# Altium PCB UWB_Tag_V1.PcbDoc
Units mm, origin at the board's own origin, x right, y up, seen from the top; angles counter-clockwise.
Board outline 86.23 x 70.61 mm, 2 copper layers (Top Layer, Bottom Layer); 71 components, 55 nets, 304 pads, 29 vias.
Unrouted connection lines stored in the file: 1.
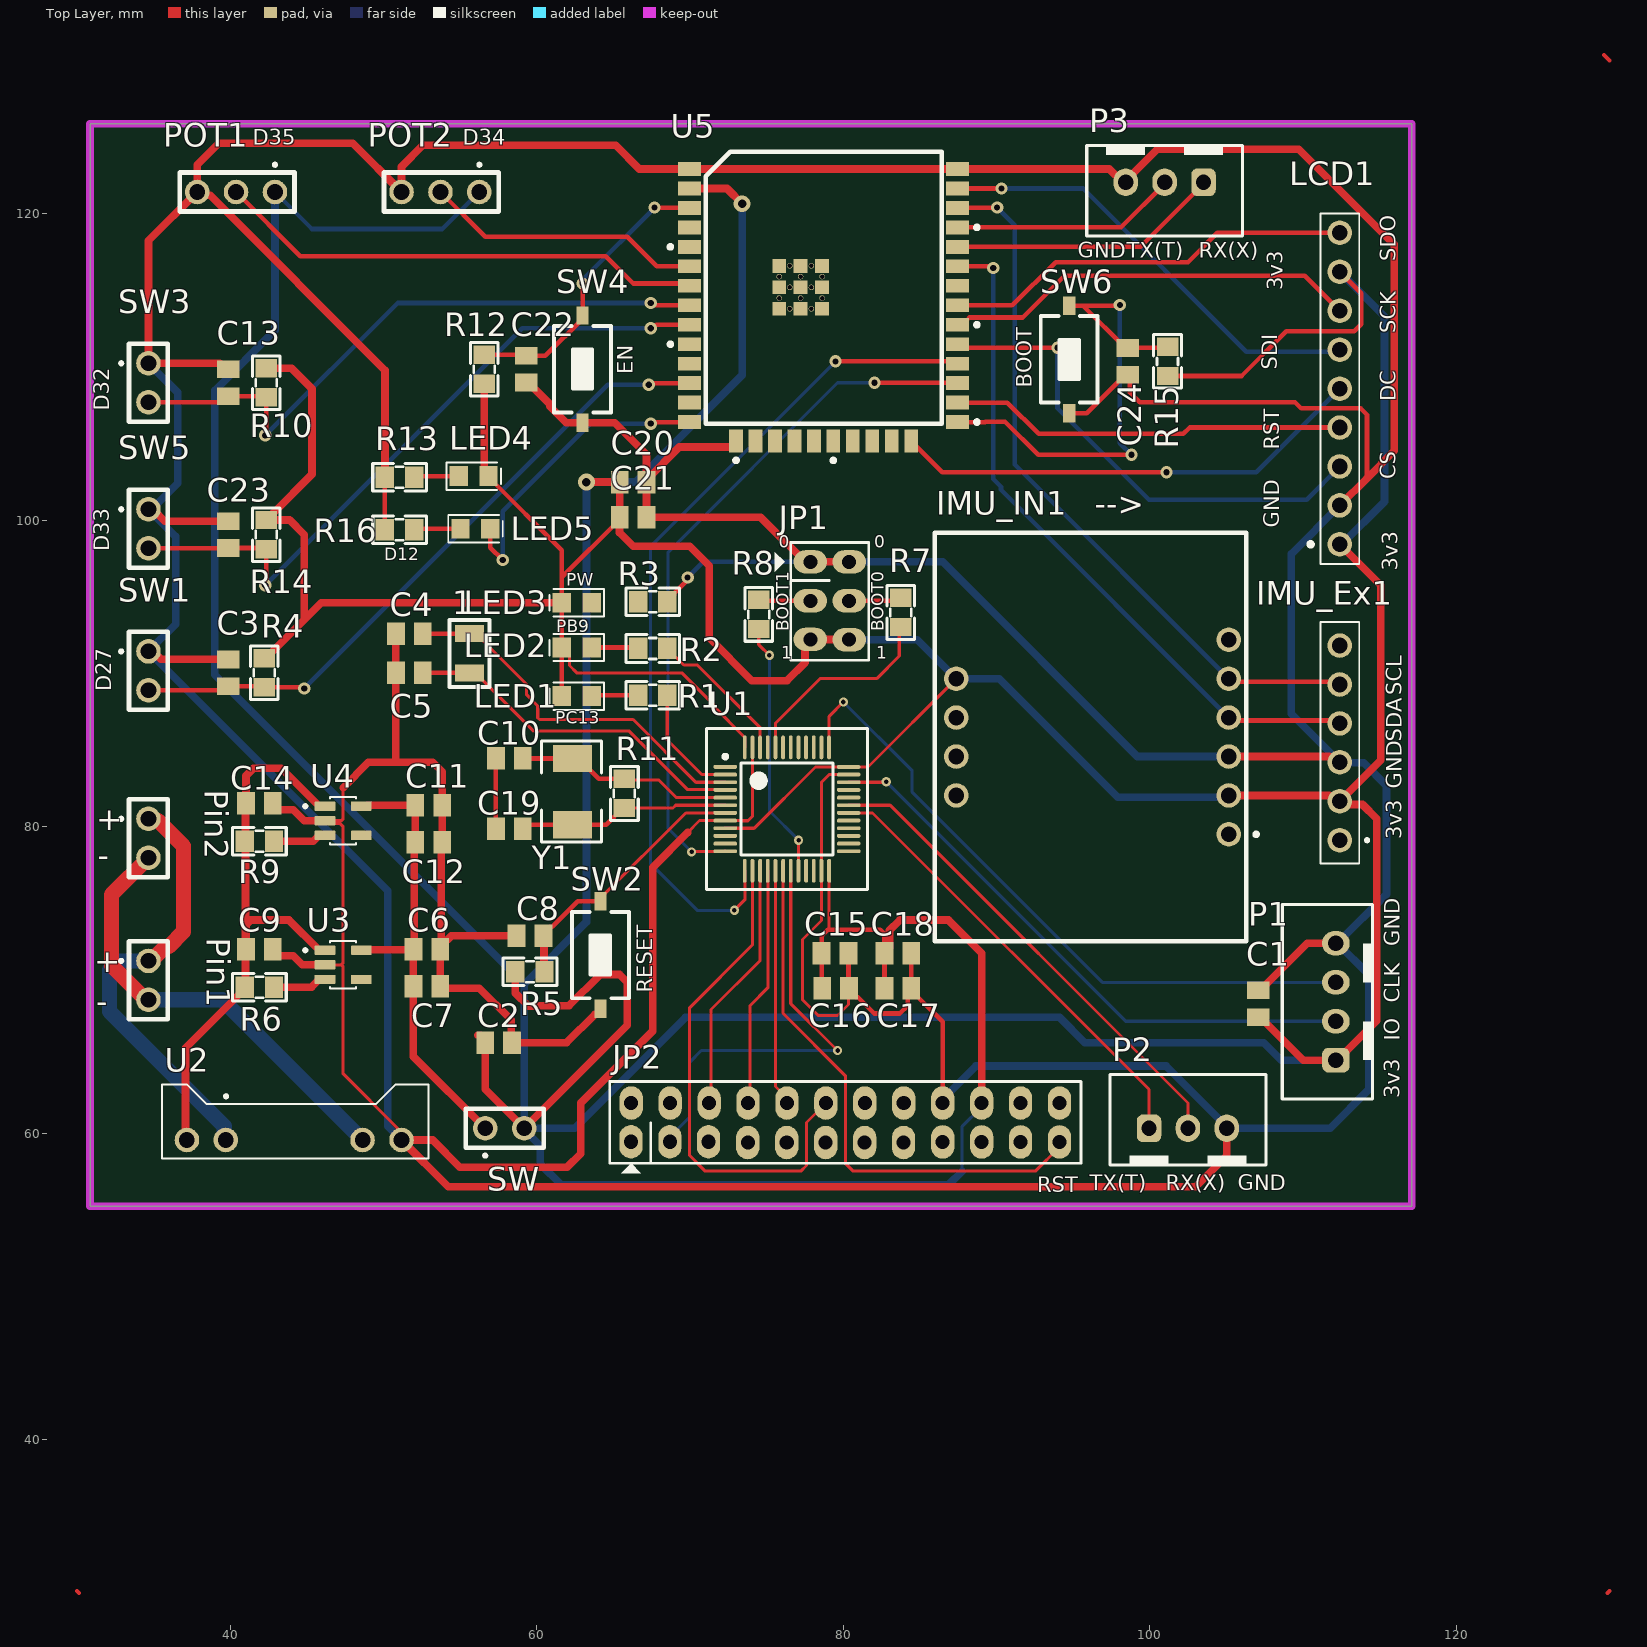
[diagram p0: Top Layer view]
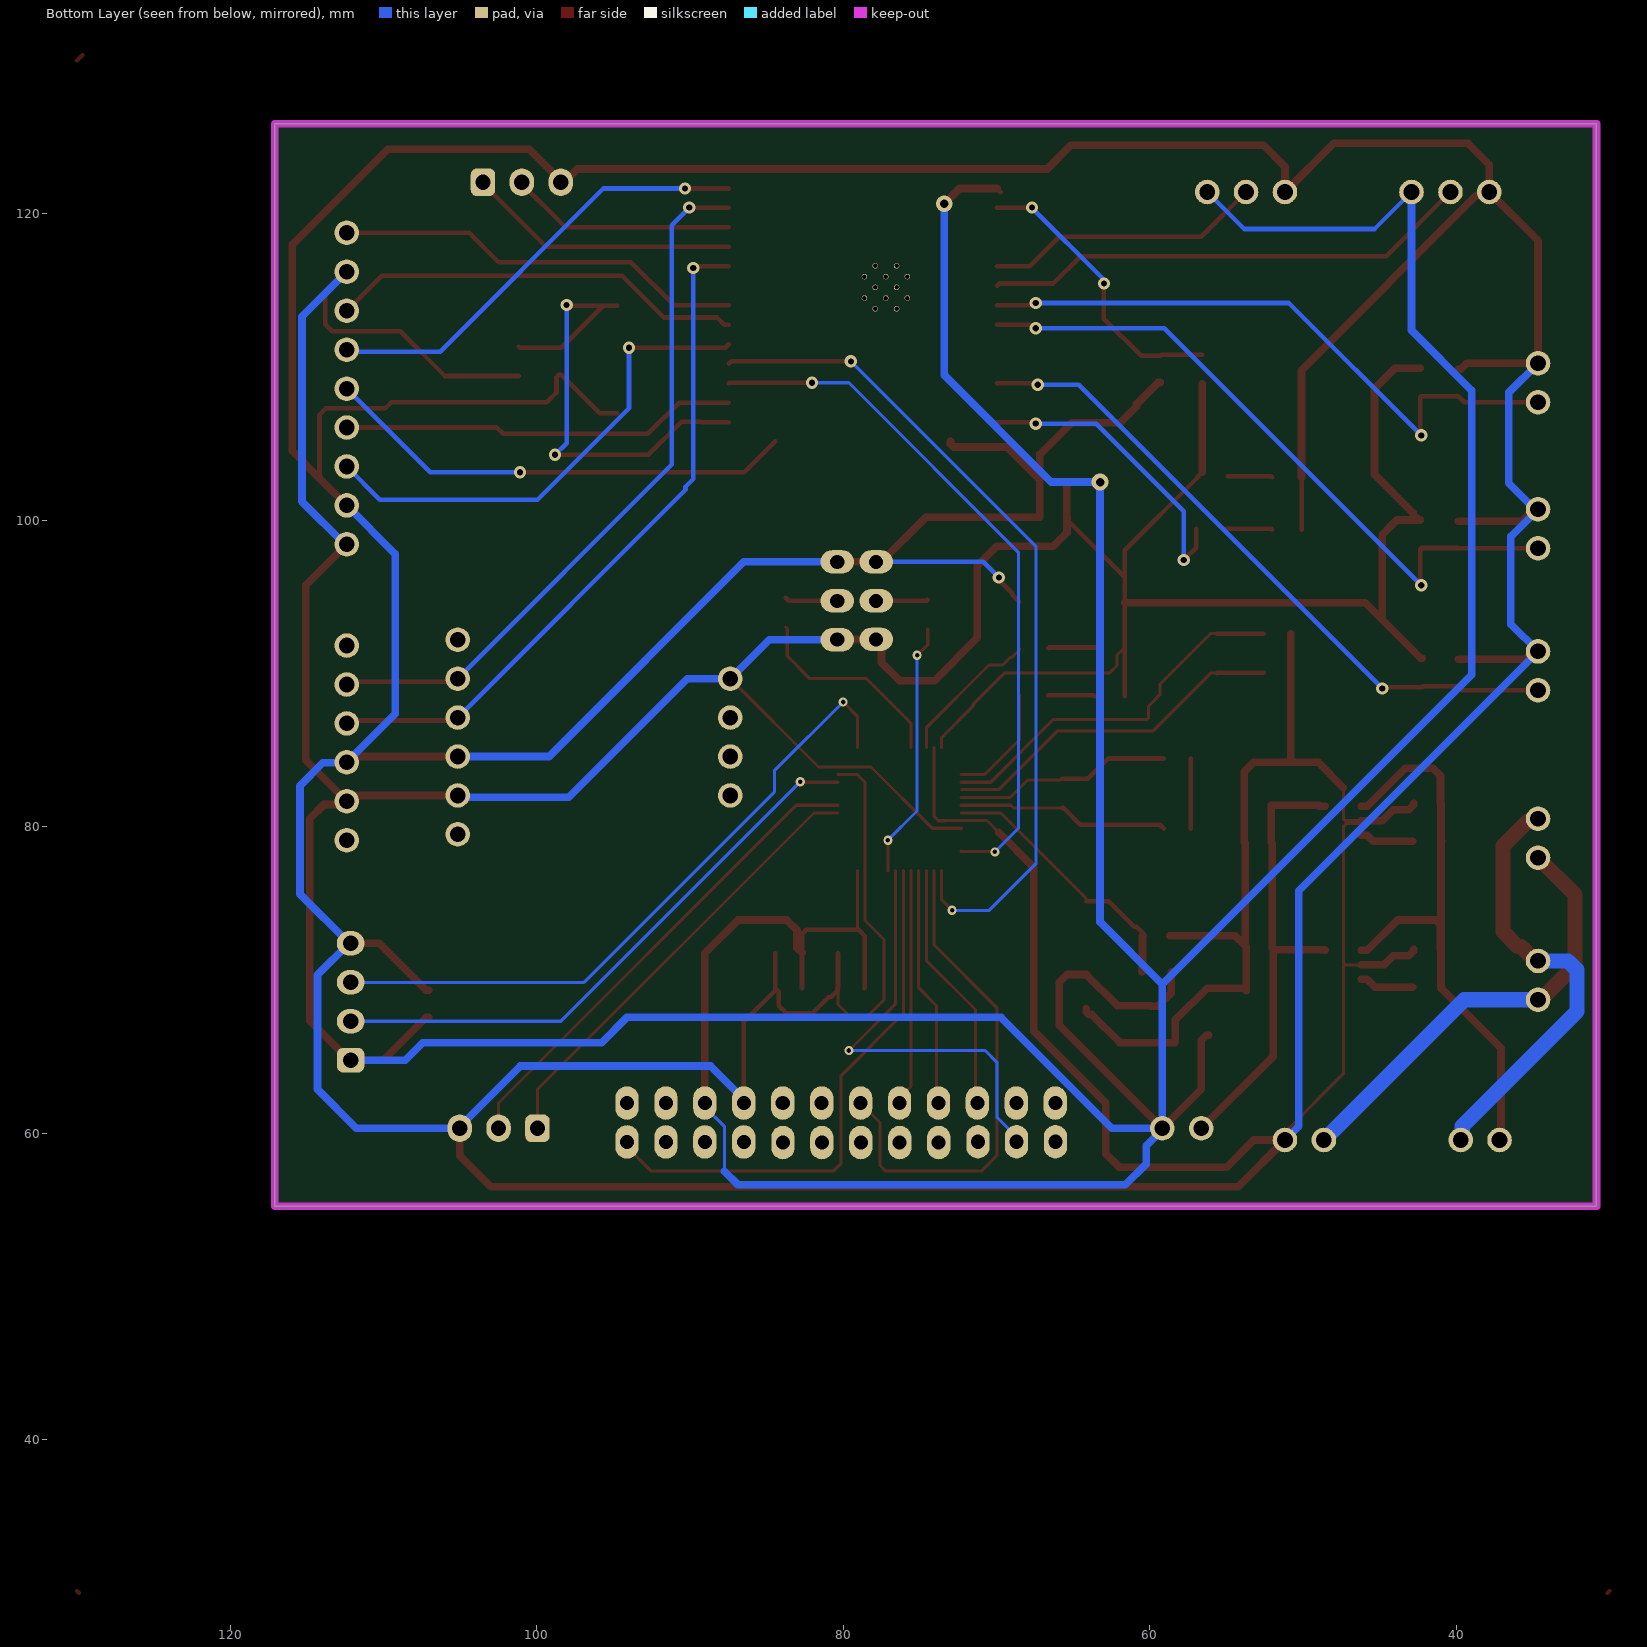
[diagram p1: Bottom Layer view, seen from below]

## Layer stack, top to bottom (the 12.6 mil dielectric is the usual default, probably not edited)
Top Solder: solder mask 0.0102, Solder Resist, Dk 3.5
Top Layer: signal copper 0.0356
Dielectric 1: dielectric 0.32, FR-4, Dk 4.8
Bottom Layer: signal copper 0.0356
Bottom Solder: solder mask 0.0102, Solder Resist, Dk 3.5

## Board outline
30.861,55.245 30.861,125.857 117.094,125.857 117.094,55.245

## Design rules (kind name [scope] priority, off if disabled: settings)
Clearance [All] p1: gap=0.2 ignorepadtopadclearanceinfootprint=FALSE
PolygonConnect [All] p1: connectstyle=Relief reliefconductorwidth=0.254 reliefentries=4 polygonreliefangle="90 Angle" airgapwidth=0.254
RoutingVias [All] p1: holewidth=0.711 width=1.27 viastyle="Through Hole" minholewidth=0.711 minwidth=1.27 maxholewidth=0.711 maxwidth=1.27
SolderMaskExpansion [All] p1: expansion=0.102 istentingtop=FALSE
Width RON [InNetClass('RON')] p1: maxlimit=0.5 minlimit=0.2 preferedwidth=0.3
Width POW [InNetClass('POW')] p2: maxlimit=1 minlimit=0.3 preferedwidth=0.5
30 further rules are at their usual default settings.

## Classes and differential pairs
net class RON: 3V3 BOOT BOOT0 BOOT1 D2/SPI_DC D4/SPI_RST D5/SPI_CS D12/LED1 D18/SPI_SCK D19/SPI_SDO D23/SPI_SDI D27 D32 D33 D34_Pot1 D35_Pot2 DB_RX DB_TX DW_IRQ DW_NSS DW_RESET EN GND MISO MOSI NetC10_1 NetJP1_2 NetJP1_5 NetLED1_2 NetLED2_2 NetLED3_2 NetLED4_2 NetLED5_2 NetR6_2 NetR9_2 O_3V3 OSCIN OSCOUT PB9 PC13 PC14 PC15 RESET RX0 SCK SCL SDA STMRX_ESPTX STMTX-ESPRX SWCLK SWIO TX0 VOUT
net class POW: VBAT+ VBAT-

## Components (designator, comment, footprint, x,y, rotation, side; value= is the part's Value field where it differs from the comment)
1 "ABS07" ABS07 55.626,91.313 r90 top
C1 "10uF" Capacitor_0805 107.061,68.453 r270 top
C2 "0.1uF" Capacitor_0805 57.517,65.913 r0 top
C3 "10uF" Capacitor_0805 39.878,90.043 r90 top
C4 "20pF" Capacitor_0805 51.689,92.583 r0 top
C5 "20pF" Capacitor_0805 51.689,90.043 r0 top
C6 "47uF" Capacitor_0805 52.832,72.009 r0 top
C7 "0.1uF" Capacitor_0805 52.832,69.596 r0 top
C8 "0.1uF" Capacitor_0805 59.563,72.898 r180 top
C9 "0.1uF" Capacitor_0805 41.91,72.009 r0 top
C10 "20pF" Capacitor_0805 58.215,84.455 r0 top
C11 "47uF" Capacitor_0805 52.959,81.407 r0 top
C12 "0.1uF" Capacitor_0805 52.959,78.994 r0 top
C13 "10uF" Capacitor_0805 39.878,108.966 r90 top
C14 "0.1uF" Capacitor_0805 41.91,81.534 r0 top
C15 "0.1uF" Capacitor_0805 79.465,71.755 r0 top
C16 "0.1uF" Capacitor_0805 79.502,69.469 r0 top
C17 "0.1uF" Capacitor_0805 83.566,69.469 r0 top
C18 "0.1uF" Capacitor_0805 83.566,71.755 r0 top
C19 "20pF" Capacitor_0805 58.215,79.883 r0 top
C20 "10uF" Capacitor_0805 66.294,102.489 r0 top
C21 "0.1uF" Capacitor_0805 66.294,100.203 r0 top
C22 "10uF" Capacitor_0805 59.309,109.855 r270 top
C23 "10uF" Capacitor_0805 39.878,99.06 r90 top
C24 "10uF" Capacitor_0805 98.552,110.363 r270 top
IMU_Ex1 "BNO055" BNO055_External 112.395,85.471 r90 top
IMU_IN1 "BNO055" BNO055_Internal 96.266,85.852 r90 top
JP1 "Connector 3x2" JP3x2 79.121,94.742 r270 top
JP2 "Connector 12x2" JP12X2_1 66.167,59.436 r0 top
LCD1 "ILI9341" ILI9341_LCD3.5 112.395,108.585 r0 top
LED1 "Led" "Led 0805 Blue" 62.611,88.519 r0 top
LED2 "Led" "Led 0805 Blue" 62.611,91.694 r0 top
LED3 "Led" "Led 0805 Blue" 62.611,94.615 r0 top
LED4 "Led" "Led 0805 Blue" 55.88,102.87 r180 top
LED5 "Led" "Led 0805 Blue" 56.007,99.441 r180 top
P1 "SWD" HDR/Header/4/BOX 112.141,68.58 r90 top
P2 "UART" HDR/Header/3/BOX 102.489,60.325 r90 top
P3 "UART" HDR/Header/3/BOX 100.965,122.047 r270 top
Pin1 "JP_1x2" JP_1x2 34.671,69.977 r270 top (schematic designator Battery1)
Pin2 "JP_1x2" JP_1x2 34.671,79.248 r270 top (schematic designator Battery2)
POT1 "JP_1x3" JP_1x3 44.323,115.951 r180 top
POT2 "JP_1x3" JP_1x3 57.658,115.951 r180 top
R1 "1k" "tro smd 0805" 67.564,88.646 r0 top
R2 "1k" "tro smd 0805" 67.564,91.694 r0 top
R3 "1k" "tro smd 0805" 67.564,94.742 r0 top
R4 "10k" "tro smd 0805" 42.164,90.043 r90 top
R5 "10k" "tro smd 0805" 59.563,70.485 r180 top
R6 "1k" "tro smd 0805" 41.91,69.596 r0 top
R7 "10k" "tro smd 0805" 83.693,93.98 r90 top
R8 "10k" "tro smd 0805" 74.549,93.853 r270 top
R9 "1k" "tro smd 0805" 41.91,79.121 r0 top
R10 "10k" "tro smd 0805" 42.291,108.966 r90 top
R11 "1M" "tro smd 0805" 65.659,82.169 r90 top
R12 "10k" "tro smd 0805" 56.642,109.855 r270 top
R13 "1k" "tro smd 0805" 51.054,102.743 r180 top
R14 "10k" "tro smd 0805" 42.291,99.06 r90 top
R15 "10k" "tro smd 0805" 101.219,110.363 r270 top
R16 "1k" "tro smd 0805" 51.054,99.314 r180 top
SW "SW_POWER" JP_1x2 57.912,60.325 r0 top (schematic designator jp_1)
SW1 "JP_1x2" JP_1x2 34.671,90.17 r270 top
SW2 "SW" SW1-SMD 64.156,71.628 r90 top value="SW chip 2 pin"
SW3 "JP_1x2" JP_1x2 34.671,108.966 r270 top
SW4 "SW" SW1-SMD 62.992,109.855 r90 top value="SW chip 2 pin"
SW5 "JP_1x2" JP_1x2 34.671,99.441 r270 top
SW6 "SW" SW1-SMD 94.742,110.49 r90 top value="SW chip 2 pin"
U1 "STM32F103C8T6" LQFP48 76.327,81.153 r270 top
U2 "TP4056_charger" TP4056_charger 44.181,48.063 r90 top
U3 "AP2112K-3.3TRG1" SOT95P285X140-5N 47.371,70.993 r0 top
U4 "AP2112K-3.3TRG1" SOT95P285X140-5N 47.371,80.391 r0 top
U5 "ESP32_WROOM_32U" ESP32_WROOM_32U 78.719,114.032 r0 top
Y1 "8Mhz" "Thach Anh 2 chan SMD5032" 62.335,82.296 r90 top value=4Mhz

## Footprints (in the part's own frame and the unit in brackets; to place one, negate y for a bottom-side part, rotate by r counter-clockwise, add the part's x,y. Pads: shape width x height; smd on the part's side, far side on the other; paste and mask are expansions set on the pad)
ABS07 [mm] "HC-49US XTAL"
  rect 1.1x1.9 smd: 1(-1.29,0) 2(1.29,0)
  silkscreen extent -2.19,-1.3 2.18,1.31, body extent -1.6,-0.75 1.6,0.75, height 0.9
BNO055_External [mm]
  round 1.6 hole 1.02 mask+0.1: 1(-6.35,0) 2(-3.81,0) 3(-1.27,0) 4(1.27,0) 5(3.81,0) 6(6.35,0)
  silkscreen extent -7.87,-1.88 7.87,1.27, body extent -8.75,-2.16 8.75,3.59, height 7.1
BNO055_Internal [mm]
  round 1.6 hole 1.02 mask+0.1: 1(-6.35,-8.89) 2(-3.81,-8.89) 3(-1.27,-8.89) 4(1.27,-8.89) 5(3.81,-8.89) 6(6.35,-8.89) 7(3.81,8.89) 8(1.27,8.89) 9(-1.27,8.89) 10(-3.81,8.89)
  silkscreen extent -13.33,-10.77 13.33,10.29, body extent -13.33,-10.12 13.33,10.29, height 9.15
Capacitor_0805 [mm]
  rect 1.16x1.47 smd: 1(-0.875,0) 2(0.875,0)
  body extent -1,-0.6 1,0.6, height 1.2
ESP32_WROOM_32U [mm]
  rect 1.5x0.9 smd: 1(-8.75,8.88) 2(-8.75,7.61) 3(-8.75,6.34) 4(-8.75,5.07) 5(-8.75,3.8) 6(-8.75,2.53) 7(-8.75,1.26) 8(-8.75,-0.01) 9(-8.75,-1.28) 10(-8.75,-2.55) 11(-8.75,-3.82) 12(-8.75,-5.09) 13(-8.75,-6.36) 14(-8.75,-7.63) 25(8.75,-7.63) 26(8.75,-6.36) 27(8.75,-5.09) 28(8.75,-3.82) 29(8.75,-2.55) 30(8.75,-1.28) 31(8.75,-0.01) 32(8.75,1.26) 33(8.75,2.53) 34(8.75,3.8) 35(8.75,5.07) 36(8.75,6.34) 37(8.75,7.61) 38(8.75,8.88)
  rect 0.9x1.5 smd: 15(-5.715,-8.88) 16(-4.445,-8.88) 17(-3.175,-8.88) 18(-1.905,-8.88) 19(-0.635,-8.88) 20(0.635,-8.88) 21(1.905,-8.88) 22(3.175,-8.88) 23(4.445,-8.88) 24(5.715,-8.88)
  rect 0.9x0.9 smd: 39_1(-2.9,2.56) 39_2(-1.5,2.56) 39_3(-0.1,2.56) 39_4(-2.9,1.16) 39_5(-1.5,1.16) 39_6(-0.1,1.16) 39_7(-2.9,-0.24) 39_8(-1.5,-0.24) 39_9(-0.1,-0.24)
  round 0.35 hole 0.3 mask+0: 40_1(-2.2,2.56) 40_2(-0.8,2.56) 40_3(-2.9,1.86) 40_4(-1.5,1.86) 40_5(-0.1,1.86) 40_6(-2.2,1.16) 40_7(-0.8,1.16) 40_8(-2.9,0.46) 40_9(-1.5,0.46) 40_10(-0.1,0.46) 40_11(-2.2,-0.24) 40_12(-0.8,-0.24)
  silkscreen extent -10.1,-10.23 10.1,10, body extent -9,-9.13 9,10.07, height 3.35
HDR/Header/3/BOX [mm]
  rrect50% 1.8x1.6 hole 1: 1(0,2.54)
  oval 1.8x1.6 hole 1: 2(0,0) 3(0,-2.54)
  silkscreen extent -2.41,-5.08 3.5,5.08, body extent -2.29,-5 3.41,5, height 7
HDR/Header/4/BOX [mm]
  rrect50% 1.6x1.8 hole 1: 1(-3.81,0)
  oval 1.6x1.8 hole 1: 2(-1.27,0) 3(1.27,0) 4(3.81,0)
  silkscreen extent -6.35,-2.41 6.35,3.5, body extent -6.25,-2.3 6.25,3.4, height 7
ILI9341_LCD3.5 [mm]
  round 1.6 hole 1.02 mask+0.1: 1(0,-10.16) 2(0,-7.62) 3(0,-5.08) 4(0,-2.54) 5(0,0) 6(0,2.54) 7(0,5.08) 8(0,7.62) 9(0,10.16)
  silkscreen extent -2.03,-11.43 1.27,11.43, body extent -3.56,-12.5 2.19,12.5, height 7.1
JP3x2 [mil] "Connector 3x2"
  oval 60x86 hole 36: 1(-100,-50) 2(0,-50) 3(99,-50) 4(-100,50) 5(0,50) 6(100,50)
  silkscreen extent -150,-141 153,100, body extent -150,-100 150,100, height 335
JP12X2_1 [mil]
  oval 60x86 hole 36: 1(-0.5,0.5) 2(99.5,0.5) 3(198.5,0.5) 4(299.5,-1.5) 5(399.5,-1.5) 6(499.5,-1.5) 7(599.5,-1.5) 8(699.5,-1.5) 9(800,0) 10(900,0) 11(1000,0) 12(1100,0) 13(0,100) 14(100,100) 15(200,100) 16(300,100) 17(400,100) 18(500,100) 19(600,100) 20(700,100) 21(800,100) 22(900,100) 23(1000,100) 24(1100,100)
  silkscreen extent -55,-80 1155,155, body extent -55,-47 1155,150, height 366
JP_1x2 [mm] "CWF2 (DS1069-1x2)"
  round 1.6 hole 1.02 mask+0.1: 1(-1.27,0) 2(1.27,0)
  silkscreen extent -2.54,-1.88 2.54,1.27, body extent -3.77,-2.2 3.73,3.55, height 7
JP_1x3 [mm] "CWF3 (DS1069-1x3)"
  round 1.6 hole 1.02 mask+0.1: 1(1.397,-5.461) 2(3.937,-5.461) 3(6.477,-5.461)
  silkscreen extent 0.13,-7.34 7.62,-4.19, body extent -1.06,-7.66 8.94,-1.9, height 7.1
"Led 0805 Blue" [mm]
  rect 1.2x1.3 smd: 1(-0.975,0) 2(0.975,0)
  silkscreen extent -1.78,-0.89 1.78,0.89, body extent -1.01,-0.62 1.01,0.63, height 1.1
LQFP48 [mm]
  oval 0.25x1.55 smd: 1(-2.75,-4.025) 2(-2.25,-4.025) 3(-1.75,-4.025) 4(-1.25,-4.025) 5(-0.75,-4.025) 6(-0.25,-4.025) 7(0.25,-4.025) 8(0.75,-4.025) 9(1.25,-4.025) 10(1.75,-4.025) 11(2.25,-4.025) 12(2.75,-4.025) 25(2.75,4.025) 26(2.25,4.025) 27(1.75,4.025) 28(1.25,4.025) 29(0.75,4.025) 30(0.25,4.025) 31(-0.25,4.025) 32(-0.75,4.025) 33(-1.25,4.025) 34(-1.75,4.025) 35(-2.25,4.025) 36(-2.75,4.025)
  oval 1.55x0.25 smd: 13(4.025,-2.75) 14(4.025,-2.25) 15(4.025,-1.75) 16(4.025,-1.25) 17(4.025,-0.75) 18(4.025,-0.25) 19(4.025,0.25) 20(4.025,0.75) 21(4.025,1.25) 22(4.025,1.75) 23(4.025,2.25) 24(4.025,2.75) 37(-4.025,2.75) 38(-4.025,2.25) 39(-4.025,1.75) 40(-4.025,1.25) 41(-4.025,0.75) 42(-4.025,0.25) 43(-4.025,-0.25) 44(-4.025,-0.75) 45(-4.025,-1.25) 46(-4.025,-1.75) 47(-4.025,-2.25) 48(-4.025,-2.75)
  silkscreen extent -5.25,-5.25 5.25,5.25, body extent -4.5,-4.5 4.5,4.5, height 1.5
SOT95P285X140-5N [mm]
  rrect15% 1.35x0.6 smd: 1(-1.185,0.95) 2(-1.185,0) 3(-1.185,-0.95) 4(1.185,-0.95) 5(1.185,0.95)
  silkscreen extent -2.57,-1.55 0.85,1.55, body extent -1.5,-1.4 1.5,1.4, height 1.4
SW1-SMD [mm]
  rect 1.2x0.8 smd: 1(-3.5,0) 2(3.5,0)
  silkscreen extent -2.82,-1.85 2.82,1.85, body extent -3.05,-1.85 3.05,1.85, height 2.5
"Thach Anh 2 chan SMD5032" [mil]
  rect 70x100 smd: 1(-85,0) 2(85,0)
  silkscreen extent -130,-75 130,80, body extent -98,-63 98,63, height 51
TP4056_charger [mm]
  round 1.6 hole 1.02 mask+0.1: 1(11.5,4.46) 2(11.5,-4.46) 3(11.5,7) 4(11.5,-7)
  silkscreen extent 10.29,-8.76 15.11,8.64, body extent -14.19,-8.76 15.11,8.64, height 9.34
"tro smd 0805" [mm]
  rect 1.2x1.4 smd: 1(-0.946,-0.061) 2(0.954,-0.061)
  silkscreen extent -1.75,-0.97 1.75,0.84, body extent -1.56,-0.76 1.44,0.64, height 0.53

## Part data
1: "SMD Quartz Crystal"
C1 C2 C3 C4 C5 C6 C7 C8 C9 C10 C11 C12 C13 C14 C15 C16 C17 C18 C19 C20 C21 C22 C23 C24: library part Capacitor_0805, "Capacitor; Ceramic; Cap; .220uF; Tol 10%; SMT; Vol-Rtg 50V; X7R; Tape And Reel"
IMU_Ex1: library part BNO055_External
JP1: library part JP3x2
JP2: library part JP12x2
LCD1: library part ILI9341_LCD3.5
LED1 LED2 LED3 LED4 LED5: "Typical LED"
P1: library part "Header 4_1", "Header, 4-Pin"
P2 P3: library part "Header 3", "Header, 3-Pin"
R1 R2 R3 R6 R9 R13 R16: library part "Tro 0805 1% 1k", "Dán"
R4 R5 R7 R8 R10 R12 R14 R15: library part "Tro 0805 1% 10k", "Dán"
R11: library part "Tro 0805 1% 1M", "Dán"
SW: library part JP_1x2
SW2 SW4 SW6: library part SW2, "Switch button 2 pin"
U1: "STM32 ARM-based 32-bit MCU with ARM 32-bit Cortex-M3 Microcontroller, 128 Kbytes Flash, 48-pin LQFP, Industrial Temperature"
U3 U4: "Linear Voltage Regulator IC Positive Fixed 1 Output 600mA SOT-25", Package="SOT-753 Diodes Inc."
U5: "Bluetooth, WiFi 802.11b/g/n, Bluetooth v4.2 +EDR, Class 1, 2 and 3 Transceiver Module 2.4GHz ~ 2.5GHz Antenna Not Included, U.FL Surface Mount"
Y1: library part "Thach Anh 2 chan SMD 5032", "Crystal For all Crystal 2pin."

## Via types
v1: diameter 0.8, hole 0.4, Top Layer to Bottom Layer, 20 vias
v2: diameter 0.6, hole 0.3, Top Layer to Bottom Layer, 7 vias
v3: diameter 1.1, hole 0.55, Top Layer to Bottom Layer, 2 vias

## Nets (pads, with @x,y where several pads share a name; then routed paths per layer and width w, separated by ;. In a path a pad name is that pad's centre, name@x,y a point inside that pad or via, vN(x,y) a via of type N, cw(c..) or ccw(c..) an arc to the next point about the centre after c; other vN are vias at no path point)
3V3: C1.2 C2.1 C15.1 C16.1 C17.1 C18.1 C20.1 C21.1 IMU_Ex1.2 IMU_IN1.2 IMU_IN1.7 JP1.3 JP1.6 JP2.22 LCD1.1 LCD1.8 LED1.1 LED2.1 LED3.1 LED4.1 P1.1 POT1.1 POT2.1 R4.2 R5.2 R10.2 R12.2 R14.2 R15.2 SW.2 U1.9 U1.24 U1.36 U1.48 U5.2 | length 559.8
  Top Layer w0.2: LED2.1 62.136,91.194 62.136,90.518 62.611,90.043 69.469,90.043 71.518,87.994 71.518,87.887 73.577,85.828 U1.48 ; U1.9 74.188,79.903 78.188,83.903 U1.36 81.617,83.903 IMU_IN1.7 ; 78.994,73.279 79.077,73.362 U1.24 ; JP2.22@89.027,61.722 JP2.22
  Top Layer w0.3: LED4.1@56.581,103.144 LED4.1 56.855,102.82 61.636,98.039 61.636,96.265 ; LED1.1 LED2.1 LED3.1 61.636,96.265 ; C21.1@65.405,100.189 65.405,100.034 61.636,96.265 ; U5.2@69.739,121.412 U5.2 ; C16.1 78.59,69.506 C15.1 78.59,72.875 78.994,73.279 82.423,73.279 82.677,73.025 82.677,71.769 C18.1 C17.1 ; R15.2 105.98,109.409 108.902,112.331 113.347,112.331 113.792,112.776 113.792,114.808 LCD1.8
  Top Layer w0.5: R4.2 42.325,90.997 45.942,94.615 LED3.1 ; R14.2 R14.2@42.452,100.014 ; R10.2 44.004,109.92 45.339,108.585 45.339,103.002 42.802,100.464 42.802,100.364 R14.2@42.452,100.014 ; 44.831,93.604 44.831,99.06 43.877,100.014 R14.2@42.452,100.014 ; C2.1@56.157,66.398 56.312,66.398 56.642,66.068 C2.1 56.642,62.865 SW.2 ; LED4.1@56.581,103.144 R12.2 ; R5.2@58.5,70.438 R5.2 58.609,69.153 59.483,68.279 59.897,68.279 59.944,68.326 62.103,68.326 64.135,70.358 65.405,70.358 65.913,69.85 65.913,67.056 SW.2 ; SW.2@59.182,60.248 SW.2 ; v3@63.627,102.489 C20.1 C21.1 C21.1@65.405,100.189 ; C21.1@65.405,100.034 65.405,99.187 66.294,98.298 69.977,98.298 71.247,97.028 71.247,92.329 74.041,89.535 76.327,89.535 77.507,90.715 77.507,91.884 JP1.3 77.864,92.215 80.378,92.215 JP1.6 ; U5.2 72.414,121.642 v3(73.406,120.65) ; C18.1@82.677,71.769 83.019,72.111 83.019,73.24 83.693,73.914 86.868,73.914 89.027,71.755 JP2.22 ; IMU_IN1.2 111.716,82.042 112.097,81.661 IMU_Ex1.2 ; C1.2 107.216,67.578 110.024,64.77 P1.1 112.241,64.77 114.808,67.337 114.808,80.518 113.875,81.451 112.605,81.451 IMU_Ex1.2 ; LCD1.1 115.062,95.758 115.062,84.328 IMU_Ex1.2
  Bottom Layer w0.2: 87.757,57.531 87.757,60.452 JP2.22@89.027,61.722
  Bottom Layer w0.3: POT1.1 45.339,118.999 53.848,118.999 POT2.1
  Bottom Layer w0.5: POT1.1 42.926,112.395 38.989,108.458 38.989,89.916 59.182,69.723 ; SW.2@59.182,60.248 60.24,59.191 60.24,57.997 61.595,56.642 86.868,56.642 87.757,57.531 ; v3(73.406,120.65) 73.406,109.474 66.421,102.489 v3(63.246,102.489) 63.246,73.787 59.182,69.723 ; JP1.6 84.836,92.202 IMU_IN1.7 90.17,89.662 97.917,81.915 105.029,81.915 IMU_IN1.2 ; P1.1 108.585,64.77 107.442,65.913 95.758,65.913 94.107,67.564 69.711,67.564 62.472,60.325 SW.2 59.182,69.723 ; LCD1.1 112.522,98.425 115.316,101.219 115.316,113.284 LCD1.8
BOOT: C24.1 R15.1 SW6.2 U5.25 | length 32.3
  Top Layer w0.3: U5.25 89.257,106.402 89.281,106.426 90.551,106.426 92.71,104.267 v1(98.806,104.267) ; SW6.2 95.645,113.99 ; v1(98.044,114.046) 97.988,113.99 95.645,113.99 ; R15.1 101.088,111.238 C24.1 98.397,111.238 95.645,113.99
  Bottom Layer w0.3: v1(98.044,114.046) 98.044,105.029 v1(98.806,104.267)
BOOT0: R7.1 U1.44 | length 13.4
  Top Layer w0.2: U1.44 75.577,86.753 78.486,89.662 82.179,89.662 83.654,91.137 83.654,92.934 R7.1
BOOT1: R8.2 U1.20 | length 16.9
  Top Layer w0.2: R8.2 74.488,91.882 v2(75.184,91.186) ; U1.20 77.077,79.109 v2(77.089,79.121)
  Bottom Layer w0.2: v2(75.184,91.186) 75.184,81.026 v2(77.089,79.121)
D2/SPI_DC: LCD1.5 U5.24 | length 31.1
  Top Layer w0.3: U5.24 86.462,103.124 v1(101.092,103.124)
  Bottom Layer w0.3: v1(101.092,103.124) 106.934,103.124 LCD1.5
D4/SPI_RST: LCD1.4 U5.26 | length 25.9
  Top Layer w0.3: U5.26 90.702,107.672 92.743,105.631 102.186,105.631 102.6,106.045 LCD1.4
D5/SPI_CS: LCD1.3 U5.29 | length 32.3
  Top Layer w0.3: U5.29 87.699,111.252 v1(93.98,111.252)
  Bottom Layer w0.3: v1(93.98,111.252) 93.98,107.315 99.949,101.346 110.236,101.346 LCD1.3
D12/LED1: LED5.1 U5.14 | length 20.1
  Top Layer w0.3: LED5.1 56.982,98.212 v1(57.785,97.409) ; v1(67.437,106.299) 67.54,106.402 U5.14
  Bottom Layer w0.3: v1(57.785,97.409) 57.785,100.584 63.5,106.299 v1(67.437,106.299)
D18/SPI_SCK: LCD1.7 U5.30 | length 27.2
  Top Layer w0.3: U5.30 87.769,112.752 88.239,113.222 91.704,113.222 94.433,115.951 110.109,115.951 LCD1.7
D19/SPI_SDO: LCD1.9 U5.31 | length 26.9
  Top Layer w0.3: U5.31 91.035,114.022 93.853,116.84 102.489,116.84 104.394,118.745 LCD1.9
D23/SPI_SDI: LCD1.6 U5.37 | length 29.5
  Top Layer w0.3: U5.37 v1(90.321,121.642) v1@90.424,121.539
  Bottom Layer w0.3: v1(90.321,121.642) 95.655,121.642 106.299,110.998 112.268,110.998 LCD1.6
D27: C3.1 R4.1 SW1.2 U5.12 | length 43.7
  Top Layer w0.2: R4.1@42.154,89.168 R4.1
  Top Layer w0.3: SW1.2 39.61,88.9 C3.1 R4.1@42.154,89.168 ; R4.1 44.761,89.097 v1(44.831,89.027) ; v1(67.31,108.839) 67.413,108.942 U5.12
  Bottom Layer w0.3: v1(44.831,89.027) 64.643,108.839 v1(67.31,108.839)
D32: C13.1 R10.1 SW3.2 U5.8 | length 41.7
  Top Layer w0.3: SW3.2 39.483,107.696 C13.1 42.281,108.091 R10.1 42.352,105.598 v1(42.291,105.537) ; v1(67.437,114.173) 67.588,114.022 U5.8
  Bottom Layer w0.3: v1(42.291,105.537) 50.927,114.173 v1(67.437,114.173)
D33: C23.1 R14.1 SW5.2 U5.9 | length 44.5
  Top Layer w0.3: SW5.2 39.864,98.171 C23.1 42.281,98.185 R14.1 42.352,95.819 v1(42.291,95.758) ; v1@67.691,112.649 67.794,112.752 U5.9
  Bottom Layer w0.3: v1(42.291,95.758) 59.055,112.522 v1(67.437,112.522)
D34_Pot1: POT2.2 U5.6 | length 18.3
  Top Layer w0.3: POT2.2 56.642,118.491 65.913,118.491 67.842,116.562 U5.6
D35_Pot2: POT1.2 U5.7 | length 32.1
  Top Layer w0.3: POT1.2 44.577,117.221 64.516,117.221 66.294,115.443 69.818,115.443 U5.7
DB_RX: P2.2 U1.31 | length 31.8
  Top Layer w0.2: U1.31 83.062,81.403 102.489,61.976 P2.2
DB_TX: P2.1 U1.30 | length 29.6
  Top Layer w0.2: U1.30 81.911,80.903 99.949,62.865 P2.1
DW_IRQ: JP2.2 U1.19 | length 28.7
  Top Layer w0.2: U1.19 76.577,68.457 v2(79.629,65.405)
  Bottom Layer w0.2: JP2.2 68.694,59.779 69.977,61.062 69.977,64.643 70.739,65.405 v2(79.629,65.405)
DW_NSS: JP2.18 U1.14 | length 33.1
  Top Layer w0.2: U1.14 74.077,72.299 69.977,68.199 69.977,58.547 70.993,57.531 77.226,57.531 77.597,57.902 77.597,60.706 JP2.18
DW_RESET: JP2.12 U1.18 | length 35.9
  Top Layer w0.2: U1.18 76.077,67.814 80.137,63.754 80.137,58.029 80.254,57.912 80.264,57.912 80.645,57.531 92.532,57.531 94.107,59.106 JP2.12
EN: C22.1 R12.1 SW4.2 U5.3 | length 18.9
  Top Layer w0.3: R12.1 59.238,110.801 C22.1 60.567,110.73 62.992,113.155 SW4.2 v1(62.992,115.443) ; v1(67.691,120.396) 69.945,120.396 U5.3
  Bottom Layer w0.3: v1(62.992,115.443) 63.088,115.539 63.088,115.793 v1(67.691,120.396)
GND: C1.1 C2.2 C3.2 C4.1 C5.1 C6.2 C7.2 C8.2 C9.2 C11.2 C12.2 C13.2 C14.2 C15.2 C16.2 C17.2 C18.2 C20.2 C21.2 C22.2 C23.2 C24.2 IMU_Ex1.3 IMU_IN1.3 JP1.1 JP1.4 JP2.21 LCD1.2 P1.4 P2.3 P3.3 POT1.3 POT2.3 R3.2 R13.2 R16.2 SW1.1 SW2.1 SW3.1 SW4.1 SW5.1 SW6.1 U1.8 U1.23 U1.35 U1.47 U2.4 U3.2 U4.2 U5.1 U5.15 U5.38 | length 645.6
  Top Layer w0.2: U3.2 47.244,70.993 ; 47.371,82.55 47.371,80.518 47.244,80.391 U4.2 46.357,80.22 47.161,80.22 47.371,80.01 47.371,71.12 47.244,70.993 ; U2.4 50.913,59.831 50.913,60.339 47.371,63.881 47.371,70.876 47.254,70.993 47.244,70.993 ; 69.85,79.629 70.624,80.403 U1.8 72.309,80.396 73.377,80.396 73.382,80.391 73.787,80.391 74.077,80.681 U1.47 ; C16.2@80.34,69.506 80.34,68.402 79.629,67.691 78.359,67.691 77.343,68.707 77.343,72.644 78.577,73.878 U1.23 78.577,80.34 78.569,80.348 78.569,82.887 79.085,83.403 U1.35
  Top Layer w0.3: R16.2 R13.2 ; R3.2 68.968,95.131 68.968,95.231 69.754,96.017 69.754,96.17 v1(69.85,96.266) ; C15.2 80.34,69.506 C16.2 80.377,69.314 80.807,68.884 80.962,68.884 82.028,67.818 83.693,67.818 84.201,68.326 84.201,69.229 C17.2 ; C18.2 C17.2 ; JP2.21 86.487,67.268 84.441,69.314 C17.2 ; SW6.1 95.899,106.99 98.397,109.488 C24.2 98.707,109.333 98.707,108.331 99.342,107.696 109.474,107.696 109.879,107.291 113.768,107.291 114.173,106.885 114.173,102.743
  Top Layer w0.5: SW1.1 34.969,91.44 35.491,90.918 C3.2 ; SW5.1 34.969,100.711 35.745,99.935 C23.2 ; C13.2 39.723,109.841 39.328,110.236 SW3.1 34.671,118.237 POT1.3 ; C9.2 42.785,71.912 43.115,71.582 44.115,71.582 44.704,70.993 U3.2 ; C14.2 42.785,81.437 43.115,81.107 44.115,81.107 44.831,80.391 U4.2 ; 47.371,82.55 49.022,84.201 50.8,84.201 ; R13.2 50.1,109.793 38.691,121.202 38.056,121.202 POT1.3 ; C4.1 C5.1 50.814,84.215 50.8,84.201 ; C7.2@53.707,69.314 53.862,69.469 56.261,69.469 58.332,67.398 58.332,65.973 C2.2 61.941,65.913 63.806,67.778 64.006,67.778 64.156,67.928 SW2.1 ; C7.2@53.707,69.469 C7.2 C6.2 53.707,72.164 C6.2@53.77,72.227 ; C8.2 54.441,72.898 C6.2@53.77,72.227 ; C22.2 59.464,108.98 60.864,107.58 60.864,107.425 61.934,106.355 SW4.1 65.095,106.355 67.169,104.281 C20.2@67.169,102.644 ; 69.85,79.629 67.564,77.343 67.564,66.675 62.865,61.976 62.865,58.674 61.976,57.785 54.991,57.785 53.213,59.563 U2.4 54.229,56.515 102.997,56.515 105.029,58.547 P2.3 ; U5.15 73.004,104.975 72.804,104.775 69.3,104.775 C20.2@67.169,102.644 ; JP1.4 JP1.1 77.521,97.282 74.6,100.203 C21.2 C20.2 C20.2@67.169,102.644 ; IMU_IN1.3 111.716,84.582 112.097,84.201 IMU_Ex1.3 ; C1.1 107.216,69.328 110.278,72.39 P1.4 ; LCD1.2 114.173,102.743 115.951,104.521 115.951,117.983 109.728,124.206 100.484,124.206 98.425,122.147 P3.3 98.227,122.047 97.362,122.912 U5.38 U5.1 66.699,122.912 65.151,124.46 52.578,124.46 51.181,123.063 POT2.3 48.006,124.587 39.243,124.587 37.846,123.19 POT1.3 ; 50.8,84.201 53.213,84.201 53.834,83.58 C11.2 C12.2 53.77,78.93 C6.2@53.77,72.227
  Bottom Layer w0.3: v1(69.85,96.266) 70.866,97.282 JP1.1
  Bottom Layer w0.5: SW3.1 36.576,108.331 36.576,102.401 34.886,100.711 SW5.1 36.449,98.933 36.449,93.218 SW1.1 50.292,75.819 50.292,60.452 U2.4 ; JP1.4 86.487,97.282 99.187,84.582 IMU_IN1.3 ; JP2.21 86.487,62.23 88.646,64.389 101.065,64.389 105.029,60.425 P2.3 111.76,60.325 114.3,62.865 114.3,70.331 P1.4@112.241,72.39 ; P1.4 P1.4@112.241,72.39 ; LCD1.2 109.22,97.79 109.22,87.376 IMU_Ex1.3 112.421,84.175 113.945,84.175 115.443,82.677 115.443,75.592 P1.4@112.241,72.39
MISO: JP2.16 U1.16 | length 16
  Top Layer w0.2: JP2.16@73.787,62.306 JP2.16 73.914,62.103 73.914,68.326 75.077,69.489 U1.16
MOSI: JP2.17 U1.17 | length 15.5
  Top Layer w0.2: U1.17 75.577,63.058 76.327,62.308 JP2.17
NetC10_1: C10.1 C19.1 | length 4.6
  Top Layer w0.3: C19.1 C10.1
NetJP1_2: JP1.2 R8.1 | length 3.4
  Top Layer w0.3: R8.1 74.545,94.742 JP1.2
NetJP1_5: JP1.5 R7.2 | length 3.4
  Top Layer w0.3: JP1.5 83.561,94.742 R7.2
NetLED1_2: LED1.2 R1.1 | length 3.1
  Top Layer w0.3: LED1.2 63.652,88.585 R1.1
NetLED2_2: LED2.2 R2.1 | length 3.1
  Top Layer w0.3: LED2.2 66.558,91.694 R2.1
NetLED3_2: LED3.2 R3.1
NetLED4_2: LED4.2 R13.1 | length 2.9
  Top Layer w0.3: R13.1 52.066,102.87 LED4.2
NetLED5_2: LED5.2 R16.1 | length 3.1
  Top Layer w0.3: R16.1 52.066,99.441 LED5.2
NetR6_2: R6.2 U3.3 | length 3.5
  Top Layer w0.5: R6.2 45.303,69.535 45.811,70.043 U3.3
NetR9_2: R9.2 U4.3 | length 3.5
  Top Layer w0.5: R9.2 45.43,79.06 45.811,79.441 U4.3
O_3V3: C6.1 C7.1 C11.1 C12.1 SW.1 U3.5 U4.5 | length 30
  Top Layer w0.5: U3.5 48.589,71.976 51.924,71.976 C6.1 52.021,72.072 52.021,78.93 C12.1 C11.1 48.997,81.407 48.931,81.341 U4.5 ; C6.1@51.957,71.976 51.957,69.469 51.957,66.802 51.957,65.01 SW.1
OSCIN: C10.2 R11.2 U1.5 Y1.2 | length 14.3
  Top Layer w0.2: R11.2 65.785,83.058 67.945,83.058 69.1,81.903 U1.5
  Top Layer w0.3: C10.2 Y1.2 62.716,84.455 64.047,83.123 R11.2
OSCOUT: C19.2 R11.1 U1.6 Y1.1 | length 13.8
  Top Layer w0.2: R11.1 68.889,81.223 69.069,81.403 U1.6
  Top Layer w0.3: C19.2 59.344,80.137 Y1.1 64.533,80.137 65.62,81.223 R11.1
PB9: R2.2 U1.46 | length 9.5
  Top Layer w0.2: R2.2 68.518,91.533 69.018,91.033 69.118,91.033 69.601,90.551 70.485,90.551 74.577,86.459 U1.46
PC13: R1.2 U1.2 | length 7.6
  Top Layer w0.2: R1.2 68.518,85.66 70.775,83.403 U1.2
PC14: 1.2 C4.2 U1.3 | length 24.6
  Top Layer w0.2: 1.2 56.026,92.603 59.348,89.281 59.348,88.607 60.071,87.884 60.071,87.112 60.188,86.995 66.294,86.995 70.386,82.903 U1.3
  Top Layer w0.3: C4.2 55.606,92.583 1.2
PC15: 1.1 C5.2 U1.4 | length 22.9
  Top Layer w0.2: 1.1 56.026,90.023 59.816,86.233 66.04,86.233 69.85,82.423 U1.4@72.282,82.423
  Top Layer w0.3: C5.2 55.606,90.043 1.1
RESET: C8.1 R5.1 SW2.2 U1.7 | length 17.8
  Top Layer w0.2: SW2.2 64.156,75.328 69.731,80.903 U1.7
  Top Layer w0.3: C8.1 60.438,73.053 60.868,73.483 61.023,73.483 62.668,75.128 SW2.2
  Top Layer w0.5: C8.1 60.473,72.863 60.473,70.581 R5.1
RX0: P3.1 U5.34 | length 17.8
  Top Layer w0.3: U5.34 99.39,117.832 103.505,121.947 P3.1
SCK: JP2.15 U1.15 | length 16.5
  Top Layer w0.2: JP2.15 71.374,62.103 71.374,68.072 74.577,71.275 U1.15
SCL: IMU_Ex1.5 IMU_IN1.5 U5.36 | length 47
  Top Layer w0.3: U5.36 87.493,120.396 v1(90.043,120.396) ; IMU_IN1.5 105.346,89.471 112.204,89.471 IMU_Ex1.5
  Bottom Layer w0.3: v1(90.043,120.396) 91.186,119.253 91.186,103.632 IMU_IN1.5
SDA: IMU_Ex1.4 IMU_IN1.4 U5.33 | length 45.5
  Top Layer w0.3: U5.33 89.686,116.562 v1(89.789,116.459) ; IMU_IN1.4 105.346,86.931 112.204,86.931 IMU_Ex1.4
  Bottom Layer w0.3: v1(89.789,116.459) 89.789,102.688 90.289,102.188 90.289,101.989 IMU_IN1.4
STMRX_ESPTX: U1.13 U5.28 | length 55.4
  Top Layer w0.2: v2(72.898,74.549) 73.577,75.228 U1.13
  Top Layer w0.3: v1(79.502,110.363) 87.318,110.363 U5.28
  Bottom Layer w0.2: v2(72.898,74.549) 70.475,74.549 67.437,77.587 67.437,98.298 v1(79.502,110.363)
STMTX-ESPRX: U1.12 U5.27 | length 45.9
  Top Layer w0.2: v2(70.104,78.359) 70.138,78.393 72.292,78.393 U1.12
  Top Layer w0.3: v1(82.042,108.966) 87.445,108.966 U5.27
  Bottom Layer w0.2: v2(70.104,78.359) 68.58,79.883 68.58,97.917 79.629,108.966 v1(82.042,108.966)
SWCLK: P1.3 U1.37 | length 43.9
  Top Layer w0.2: U1.37 79.077,87.205 v2(80.01,88.138)
  Bottom Layer w0.2: v2(80.01,88.138) 84.493,83.655 84.493,82.258 96.901,69.85 P1.3
SWIO: P1.2 U1.34 | length 38.3
  Top Layer w0.2: U1.34 v2@82.578,82.903 ; P1.2@111.957,67.126 P1.2
  Bottom Layer w0.2: v2(82.804,82.931) 98.425,67.31 P1.2
TX0: P3.2 U5.35 | length 14.8
  Top Layer w0.3: U5.35 98.12,119.102 100.965,121.947 P3.2
VBAT+: Pin1.1 Pin2.1 U2.1 | length 29
  Top Layer w1: Pin1.1 34.833,71.247 35.777,72.191 35.996,72.191 36.957,73.152 36.957,78.74 35.294,80.403 34.786,80.403 Pin2.1
  Bottom Layer w1: Pin1.1@34.556,71.132 Pin1.1 32.717,71.247 32.131,70.661 32.131,67.945 39.606,60.47 39.606,59.635 U2.1@39.751,59.49
VBAT-: Pin1.2 Pin2.2 U2.2 | length 28.9
  Top Layer w1: Pin1.2 34.509,68.707 32.858,70.358 32.844,70.358 32.258,70.944 32.258,75.565 Pin2.2
  Bottom Layer w1: Pin1.2 39.497,68.707 U2.2@48.445,59.759
VOUT: C9.1 C14.1 R6.1 R9.1 U2.3 U3.1 U4.1 | length 39.6
  Top Layer w0.5: U2.3@37.084,59.51 37.084,65.555 40.964,69.435 R6.1 41,69.571 41,71.974 C9.1 ; U3.1 45.811,71.943 43.84,73.914 41.328,73.914 41.035,73.621 C9.1 ; U4.1 45.811,81.341 43.332,83.82 41.529,83.82 41.035,83.326 C14.1 41,81.499 41,79.096 R9.1 41,79.025 41,73.621 41,72.044 C9.1
pads on no net: IMU_Ex1.1 IMU_Ex1.6 IMU_IN1.1 IMU_IN1.6 IMU_IN1.8 IMU_IN1.9 IMU_IN1.10 JP2.1 JP2.3 JP2.4 JP2.5 JP2.6 JP2.7 JP2.8 JP2.9 JP2.10 JP2.11 JP2.13 JP2.14 JP2.19 JP2.20 JP2.23 JP2.24 U1.1 U1.10 U1.11 U1.21 U1.22 U1.25 U1.26 U1.27 U1.28 U1.29 U1.32 U1.33 U1.38 U1.39 U1.40 U1.41 U1.42 U1.43 U1.45 U3.4 U4.4 U5.4 U5.5 U5.10 U5.11 U5.13 U5.16 U5.17 U5.18 U5.19 U5.20 U5.21 U5.22 U5.23 U5.32 U5.39_1 U5.39_2 U5.39_3 U5.39_4 U5.39_5 U5.39_6 U5.39_7 U5.39_8 U5.39_9 U5.40_1 U5.40_2 U5.40_3 U5.40_4 U5.40_5 U5.40_6 U5.40_7 U5.40_8 U5.40_9 U5.40_10 U5.40_11 U5.40_12
copper on no net: | length 0.9
  Top Layer w0.254: 30,30.149 30.149,30 ; 129.641,130.359 130,130 ; 129.851,30 130,30.149

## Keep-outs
Keep-Out Layer:
  the board outline again, w0.5

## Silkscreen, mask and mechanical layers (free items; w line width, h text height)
Top Overlay:
  text "D35" at 41.466,124.483 h1
  text "D34" at 55.182,124.483 h1
  text "GND" at 95.314,117.117 h1
  text "TX(T)" at 98.501,117.117 h1
  text "RX(X)" at 103.2,117.117 h1
  text "SDO" at 116.055,116.904 h1 r90
  text "3v3" at 108.689,114.999 h1 r90
  text "SCK" at 116.055,112.205 h1 r90
  text "SDI" at 108.308,109.832 h1 r90
  text "EN" at 66.271,109.53 h1 r90
  text "BOOT" at 92.306,108.657 h1 r90
  text "DC" at 116.055,107.752 h1 r90
  text "D32" at 32.108,107.125 h1 r90
  text "RST" at 108.435,104.585 h1 r90
  text "CS" at 116.055,102.672 h1 r90
  text "-->" at 96.424,100.326 h1.5
  text "GND" at 108.435,99.505 h1 r90
  text "0" at 75.806,98.194 h0.8
  text "0" at 82.029,98.194 h0.8
  text "D33" at 32.108,97.981 h1 r90
  text "D12" at 50.054,97.382 h0.8
  text "3v3" at 116.182,96.711 h1 r90
  text "PW" at 61.945,95.731 h0.8
  text "BOOT1" at 76.431,92.755 h0.8 r90
  text "BOOT0" at 82.654,92.749 h0.8 r90
  text "PB9" at 61.291,92.683 h0.8
  text "1" at 75.94,90.955 h0.8
  text "1" at 82.163,90.955 h0.8
  text "D27" at 32.235,88.837 h1 r90
  text "SCL" at 116.436,88.583 h1 r90
  text "PC13" at 61.211,86.714 h0.8
  text "SDA" at 116.436,85.535 h1 r90
  text "GND" at 116.436,82.487 h1 r90
  text "+" at 31.25,79.783 h1.5
  text "3v3" at 116.436,79.185 h1 r90
  text "-" at 31.377,77.378 h1.5
  text "GND" at 116.309,72.2 h1 r90
  text "+" at 31.123,70.512 h1.5
  text "RESET" at 67.541,69.168 h1 r90
  text "CLK" at 116.309,68.517 h1 r90
  text "-" at 31.25,67.853 h1.5
  text "IO" at 116.309,66.052 h1 r90
  text "3v3" at 116.309,62.294 h1 r90
  text "TX(T)" at 96.088,56.284 h1
  text "RX(X)" at 101.041,56.284 h1
  text "GND" at 105.728,56.284 h1
  text "RST" at 92.647,56.157 h1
